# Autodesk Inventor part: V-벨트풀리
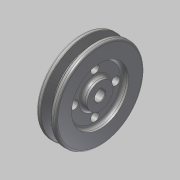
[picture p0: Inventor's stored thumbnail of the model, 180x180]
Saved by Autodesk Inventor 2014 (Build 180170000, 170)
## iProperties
Created: 2015-09
Part Number: V-벨트풀리
Material: 강철, 연강
Document SubType Name: Modeling
Designer: mduedu
Density: 1 g/cm^3
Appearance: 강철
Author: mduedu
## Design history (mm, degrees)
sketch "스케치1"
  geometry: L1 (-9.5, 0)-(9.5, 0); L2 (-9.5, 0)-(-9.5, 42.7); L3 (-9.5, 42.7)-(-4.877, 42.7); L4 (-4.877, 42.7)-(-1.953, 33.7); L5 (-1.953, 33.7)-(1.953, 33.7); L6 (1.953, 33.7)-(4.877, 42.7); L7 (4.877, 42.7)-(9.5, 42.7); L8 (9.5, 42.7)-(9.5, 0); L9 (0, 0)-(0, 33.7); L10 (-9.5, 40)-(9.5, 40); 3 further points
  constraints: 20 end point, 6 point on line, 3 perpendicular, 2 midpoint, 2 parallel, 2 symmetric about line, 1 coincident, 1 collinear, 1 equal length, 1 horizontal, 1 vertical, 1 vertical alignment
  dimensions: "d0" = 19 distance between parallel lines of L8 L2; "d5" = 6.3 distance between parallel lines of L5 L10; "d6" = 8 distance of point (4, 40) point (-4, 40); "d7" = 36 deg angle of L6 L4; "d40" = 2.7 distance between parallel lines of L10 L3; "d82" = 80 diameter of L10 L1; "d83" = 85.4 diameter of L3 L1 (derived)
revolve "회전1" sketch "스케치1" stored, may be unused: angle "d8" = 90 deg
sketch "스케치2"
  geometry: C1 r 12.5 at (0, 0); C2 r 27.5 at (0, 0); 1 further point
  constraints: 2 centre point, 2 coincident
  dimensions: "d9" = 25 diameter of C1; "d41" = 55 diameter of C2
extrude "돌출5" cut sketch "스케치2" distance "d42" = 5; taper "d43" = 0 deg
hole "구멍2" diameter "d46" = 10; stored, may be unused: countersink angle "d50" = 90 deg, drill point angle "d52" = 118 deg; dims "d47" = 6, "d48" = 4, "d49" = 2, "d51" = 8, "d84" = 10, "d85" = 10
sketch "스케치8"
  geometry: L1 (-1.5, 4.77)-(1.5, 4.77); L2 (1.5, 4.77)-(1.5, 6.4); L3 (1.5, 6.4)-(-1.5, 6.4); L4 (-1.5, 6.4)-(-1.5, 4.77); A1 r 5 centre (0, 0) between (-1.5, 4.77) and (1.5, 4.77) reference; 1 further point
  constraints: 8 end point, 2 parallel, 2 point on circle, 1 horizontal, 1 perpendicular
  dimensions: "d53" = 3 distance of L2.end L3.end; "d55" = 11.4 dimension on A1 L3
extrude "돌출6" cut sketch "스케치8" stored distance "d56" = 5; taper "d57" = 0 deg
fillet "모깎기5" dims "d71" = 2, "d72" = 1, "d73" = 0.5
fillet "모깎기7" dims "d75" = 3
fillet "모깎기8" dims "d76" = 3
sketch "스케치10"
  geometry: C1 r 35 at (0, 0); 1 further point
  constraints: 1 centre point, 1 coincident, 1 other
  dimensions: "d77" = 70 diameter of C1
extrude "돌출8" join sketch "스케치10" distance "d80" = 0.5; taper "d81" = 0 deg
chamfer "모따기4" distance "d88" = 0.5; stored, may be unused: second distance "d89" = 2, angle "d90" = 45 deg
sketch "스케치11" dims "d91" = 40
  geometry: C1 r 4 at (0, 20); 2 further points
  constraints: 2 vertical alignment, 1 centre point, 1 coincident, 2 other
  dimensions: "d92" = 8 diameter of C1
extrude "돌출9" cut sketch "스케치11" stored distance "d93" = 10; taper "d94" = 0 deg
node "솔리드1"
mirror "대칭2"
pattern_circular "원형 패턴2" dims angle "d96" = 360 deg
